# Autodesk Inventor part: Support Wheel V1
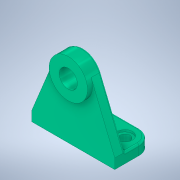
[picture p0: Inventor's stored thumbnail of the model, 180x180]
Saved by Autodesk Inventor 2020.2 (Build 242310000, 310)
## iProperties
Created: 2018-06
Part Number: Support Wheel V1
Material: Iron, Cast
Document SubType Name: Modeling
Designer: Power User
Density: 7.15 g/cm^3
Appearance: Aluminum - Polished(1)
Mass: 471.804 g
Surface Area: 175.665 cm^2
Volume: 65.9865 cm^3
Author: Power User
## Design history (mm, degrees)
sketch "Sketch1"
  geometry: L1 (0, 0)-(0, 60); L2 (-41, 0)-(-41, 10); L3 (-41, 10)-(-17.584, 67.199); L4 (-41, 0)-(0, 0); L5 (41, 10)-(17.584, 67.199); L6 (41, 0)-(41, 10); L7 (41, 0)-(0, 0); L8 (-41, 10)-(41, 10); A1 r 19 centre (0, 60) between (-17.584, 67.199) and (17.584, 67.199)
  constraints: 16 end point, 3 symmetric about line, 3 vertical, 2 point on circle, 1 centre point, 1 coincident, 1 horizontal, 1 tangent
  dimensions: "d0" = 60 distance of L1.start L1.end; "d1" = 38 diameter of A1; "d2" = 10 distance of L2.start L2.end; "d3" = 82 diameter of L2 L1
extrude "Extrusion2" new body sketch "Sketch1" distance "d7" = 10; taper "d8" = 0 deg
extrude "Extrusion3" join sketch "Sketch1" distance "d9" = 38; taper "d10" = 0 deg
extrude "Extrusion4" join sketch "Sketch1" distance "d11" = 5; taper "d12" = 0 deg
sketch "Sketch2"
  geometry: C1 r 19 at (0, 0) reference; 2 further points
  constraints: 1 coincident
hole "Hole1" sketch "Sketch2" at (0, 0) diameter "d13" = 18; stored, may be unused: countersink angle "d17" = 90 deg, drill point angle "d19" = 118 deg; dims "d14" = 6, "d15" = 4, "d16" = 2, "d18" = 8
fillet "Fillet1" dims "d20" = 14
node "Hole4"
sketch "Sketch3"
  geometry: A1 r 14 centre (14, 14) between (14, 28) and (0, 14) reference; A2 r 14 centre (68, 14) between (82, 14) and (68, 28) reference; 3 further points
  constraints: 2 coincident
hole "Hole2" sketch "Sketch3" at (14, 14), (68, 14) diameter "d21" = 10; stored, may be unused: countersink angle "d25" = 90 deg, drill point angle "d27" = 118 deg; dims "d22" = 6, "d23" = 15, "d24" = 2, "d26" = 8
fillet "Fillet2" dims "d28" = 2
body "Solid2"
sketch "Sketch4"
  geometry: 1 further point
hole "Hole3" sketch "Sketch4" diameter "d29" = 9; stored, may be unused: countersink angle "d33" = 90 deg, drill point angle "d35" = 0 deg; dims "d30" = 6, "d31" = 4, "d32" = 2, "d34" = 8
